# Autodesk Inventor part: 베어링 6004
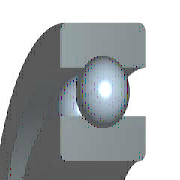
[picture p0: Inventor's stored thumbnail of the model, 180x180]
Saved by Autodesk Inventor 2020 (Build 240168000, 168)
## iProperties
Created: 2012-02
Part Number: 베어링 6004
Material: 강철, 연강
Description: 깊은 그루브 볼 베어링
Document SubType Name: Modeling
Standard: KS B 2023
Designer: mduedu
Standards Organization: KS
Language: ko-KR
Size Designation: 6004 - 20 x 42 x 12
Categories: <MemberInstance><Categories><Category DisplayName="샤프트 부품" InternalName="7f7aeb1f-a693-4053-b835-cee3144e0d98" Mnemonic="SHFT"><Category DisplayName="베어링" Inter
Density: 1 g/cm^3
Appearance: 노란색
IsCustomPart: 1
Author: mduedu
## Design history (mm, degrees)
sketch "스케치" dims "d0" = 5.72 (= -0.26 x WD + 0.26 x BD)
  geometry: L1 (3.14, 15.5)-(8.86, 15.5); L2 (6, 15.5)-(6, 12.64); L3 (6, 15.5)-(6, 18.36); L4 (3.875, 13.586)-(0, 13.586); L5 (0, 10)-(12, 10); L6 (3.875, 17.414)-(0, 17.414); L7 (0, 21)-(12, 21); L8 (12, 10)-(12, 13.586); L9 (8.125, 13.586)-(12, 13.586); L10 (8.125, 17.414)-(12, 17.414); L11 (12, 21)-(12, 17.414); L12 (-1.4, 0)-(8.4, 0) reference; L13 (0, -0.3)-(0, 5.3) reference
  constraints: 22 end point, 4 point on line, 2 collinear, 2 perpendicular, 2 symmetric about line, 1 midpoint, 1 parallel, 14 other
  dimensions: "d9" = 20 diameter of L5 L12 (= WD); "d11" = 42 diameter of L7 L12 (= BD); "d12" = 12 distance between parallel lines of L8 L13 (= KB); "d13" = 27.172 diameter of L9 L12 (= 0.326 x BD + 0.674 x WD)
revolve "본체" stored, may be unused: angle "d6" = 90 deg
revolve "볼" stored, may be unused: angle "d7" = 90 deg
pattern_circular "IDS_ARRAYBALL[SIMPL:T]" dims angle "d3" = 360 deg
body "Solid1"
fillet "모깎기1" dims "d1" = 0.6 (= KRS)
other parameters: "WD" = 20 [user parameter; used in 5 equation terms], "BD" = 42 [user parameter; used in 5 equation terms], "KB" = 12 [user parameter; used in 1 equation term], "KRS" = 0.6 [user parameter; used in 1 equation term], "d4" = 0, "d5" = 0, "d8" = 0, "d14" = 0, "d15" = 0, "BBA" = 0 [user parameter], "BC0" = 5000000 [user parameter], "BC" = 9360000 [user parameter], "BR" = 21 (= 0.5 x BD) [user parameter]
